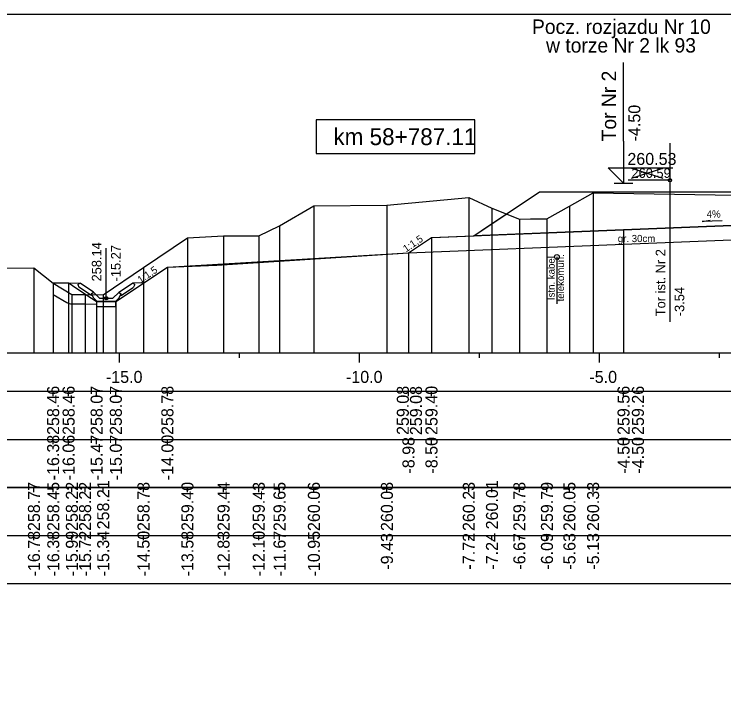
# Model space of a CAD drawing. Extents: x 6516023 to 6560129, y 5513077 to 5529206.
# Drawn here: x 6516933.52 to 6516948.3, y 5514498.91 to 5514513.16 of the extents above; entities that cross this region are included whole.
import ezdxf

# ---------------------------------------------------------------- set-up
doc = ezdxf.new("R2010")
doc.units = 0
for name, color, linetype in [('IR_default', 7, 'Continuous'), ('TOR_PRZEK_P-kable', 7, 'Continuous'), ('TOR_PRZEK_P-komponent', 7, 'Continuous'), ('TOR_PRZEK_P-odwodnienie', 7, 'Continuous'), ('TOR_PRZEK_P-opisy', 7, 'Continuous'), ('TOR_PRZEK_P-tabelka istniejace', 7, 'Continuous'), ('TOR_PRZEK_P-tabelka projektowane', 7, 'Continuous'), ('TOR_PRZEK_P-teren istniejacy', 7, 'Continuous'), ('TOR_PRZEK_P-tory istniejace', 7, 'Continuous'), ('TOR_PRZEK_P-tory projektowane', 7, 'Continuous'), ('TOR_PRZEK_P-uklad odniesienia', 7, 'Continuous'), ('TOR_PRZEK_P-warstwa ochronna I', 7, 'Continuous'), ('TOR_PRZEK_P-warstwa ochronna II', 7, 'Continuous'), ('TOR_PS_T-skarpy projektowane', 7, 'Continuous'), ('TOR_RAMKI-ramka+tabelka 1', 7, 'Continuous')]:
    doc.layers.add(name, color=color, linetype=linetype)

msp = doc.modelspace()

# ---------------------------------------------------------------- linework, layer by layer
at = {"layer": 'IR_default'}
msp.add_lwpolyline([(6516934.332, 5514507.567), (6516934.588, 5514507.564), (6516934.655, 5514507.563), (6516934.726, 5514507.516), (6516934.745, 5514507.503), (6516935.135, 5514507.243), (6516935.24, 5514507.173), (6516935.555, 5514507.173), (6516935.64, 5514507.173), (6516936.487, 5514507.738), (6516936.713, 5514507.889), (6516937.739, 5514507.93), (6516941.734, 5514508.19), (6516941.734, 5514508.19), (6516942.213, 5514508.509), (6516942.399, 5514508.516), (6516943.093, 5514508.544), (6516943.382, 5514508.737), (6516944.463, 5514509.458), (6516945.202, 5514509.458), (6516947.963, 5514509.458), (6516948.174, 5514509.458), (6516948.963, 5514509.458)], dxfattribs=at)
at = {"layer": 'TOR_PRZEK_P-kable'}
msp.add_line((6516944.825, 5514508.104), (6516944.825, 5514507.13), dxfattribs=at)
msp.add_circle((6516944.825, 5514508.104), 0.05, dxfattribs=at)
at = {"layer": 'TOR_PRZEK_P-komponent'}
msp.add_lwpolyline([(6516944.463, 5514509.458), (6516947.963, 5514509.458), (6516948.963, 5514509.458), (6516952.463, 5514509.458), (6516953.013, 5514509.458), (6516956.513, 5514509.458), (6516957.598, 5514508.735), (6516954.013, 5514508.878), (6516952.763, 5514508.928), (6516952.713, 5514508.929), (6516951.463, 5514508.879), (6516950.713, 5514508.849), (6516948.463, 5514508.759), (6516946.213, 5514508.669), (6516943.093, 5514508.544)], close=True, dxfattribs=at)
at = {"layer": 'TOR_PRZEK_P-odwodnienie'}
for p, q in [((6516935.439, 5514507.243), (6516935.439, 5514508.287)), ((6516935.13, 5514507.302), (6516934.869, 5514507.477)), ((6516935.175, 5514507.369), (6516934.894, 5514507.556)), ((6516935.704, 5514507.369), (6516935.984, 5514507.556)), ((6516935.748, 5514507.302), (6516936.01, 5514507.477)), ((6516935.142, 5514507.319), (6516935.13, 5514507.302)), ((6516935.132, 5514507.338), (6516935.179, 5514507.362)), ((6516935.175, 5514507.369), (6516935.166, 5514507.357)), ((6516935.299, 5514507.243), (6516935.179, 5514507.362)), ((6516935.579, 5514507.243), (6516935.699, 5514507.362)), ((6516935.699, 5514507.362), (6516935.747, 5514507.338)), ((6516935.704, 5514507.369), (6516935.712, 5514507.357)), ((6516935.737, 5514507.319), (6516935.748, 5514507.302)), ((6516935.249, 5514507.173), (6516935.629, 5514507.173)), ((6516935.299, 5514507.243), (6516935.579, 5514507.243))]:
    msp.add_line(p, q, dxfattribs=at)
for points in [[(6516934.648, 5514507.568), (6516934.894, 5514507.556)], [(6516934.844, 5514507.529), (6516934.894, 5514507.556)], [(6516934.844, 5514507.529), (6516934.869, 5514507.477)], [(6516936.231, 5514507.568), (6516935.984, 5514507.556)], [(6516936.035, 5514507.529), (6516935.984, 5514507.556)], [(6516936.035, 5514507.529), (6516936.01, 5514507.477)], [(6516935.166, 5514507.357), (6516935.131, 5514507.338)], [(6516935.131, 5514507.338), (6516935.142, 5514507.319)], [(6516935.179, 5514507.243), (6516935.132, 5514507.338)], [(6516935.699, 5514507.243), (6516935.747, 5514507.338)], [(6516935.712, 5514507.357), (6516935.748, 5514507.338)], [(6516935.748, 5514507.338), (6516935.737, 5514507.319)], [(6516935.249, 5514507.173), (6516935.179, 5514507.243)], [(6516935.24, 5514507.173), (6516935.239, 5514507.174), (6516935.24, 5514507.173), (6516935.239, 5514507.173), (6516935.24, 5514507.173), (6516935.24, 5514507.173), (6516935.24, 5514507.173), (6516935.24, 5514507.174)], [(6516935.239, 5514507.173), (6516935.239, 5514507.174), (6516935.239, 5514507.173), (6516935.239, 5514507.173), (6516935.239, 5514507.173), (6516935.24, 5514507.173), (6516935.239, 5514507.173), (6516935.24, 5514507.174)], [(6516935.639, 5514507.173), (6516935.239, 5514507.173), (6516935.239, 5514507.073), (6516935.639, 5514507.073), (6516935.639, 5514507.173)], [(6516935.629, 5514507.173), (6516935.699, 5514507.243)], [(6516935.64, 5514507.173), (6516935.639, 5514507.174), (6516935.64, 5514507.173), (6516935.639, 5514507.173), (6516935.64, 5514507.173), (6516935.64, 5514507.173), (6516935.64, 5514507.173), (6516935.64, 5514507.174)], [(6516935.639, 5514507.173), (6516935.639, 5514507.174), (6516935.639, 5514507.173), (6516935.639, 5514507.173), (6516935.639, 5514507.173), (6516935.64, 5514507.173), (6516935.639, 5514507.173), (6516935.64, 5514507.174)]]:
    msp.add_lwpolyline(points, dxfattribs=at)
msp.add_circle((6516935.439, 5514507.243), 0.035, dxfattribs=at)
at = {"layer": 'TOR_PRZEK_P-opisy'}
msp.add_lwpolyline([(6516948.268, 5514508.857), (6516947.85, 5514508.838), (6516948.018, 5514508.866)], dxfattribs=at)
at = {"layer": 'TOR_PRZEK_P-tabelka istniejace'}
for p, q in [((6516933.933, 5514503.206), (6516933.933, 5514503.306)), ((6516934.336, 5514503.206), (6516934.336, 5514503.306)), ((6516934.723, 5514503.206), (6516934.723, 5514503.306)), ((6516934.998, 5514503.206), (6516934.998, 5514503.306)), ((6516935.375, 5514503.206), (6516935.375, 5514503.306)), ((6516936.215, 5514503.206), (6516936.215, 5514503.306)), ((6516937.13, 5514503.206), (6516937.13, 5514503.306)), ((6516937.882, 5514503.206), (6516937.882, 5514503.306)), ((6516938.616, 5514503.206), (6516938.616, 5514503.306)), ((6516939.048, 5514503.206), (6516939.048, 5514503.306)), ((6516939.764, 5514503.206), (6516939.764, 5514503.306)), ((6516941.285, 5514503.206), (6516941.285, 5514503.306)), ((6516942.99, 5514503.206), (6516942.99, 5514503.306)), ((6516943.473, 5514503.206), (6516943.473, 5514503.306)), ((6516944.043, 5514503.206), (6516944.043, 5514503.306)), ((6516944.618, 5514503.206), (6516944.618, 5514503.306)), ((6516945.086, 5514503.206), (6516945.086, 5514503.306)), ((6516945.579, 5514503.206), (6516945.579, 5514503.306)), ((6516909.663, 5514502.306), (6516993.463, 5514502.306)), ((6516933.933, 5514502.206), (6516933.933, 5514502.306)), ((6516934.336, 5514502.206), (6516934.336, 5514502.306)), ((6516934.723, 5514502.206), (6516934.723, 5514502.306)), ((6516934.998, 5514502.206), (6516934.998, 5514502.306)), ((6516935.375, 5514502.206), (6516935.375, 5514502.306)), ((6516936.215, 5514502.206), (6516936.215, 5514502.306)), ((6516937.13, 5514502.206), (6516937.13, 5514502.306)), ((6516937.882, 5514502.206), (6516937.882, 5514502.306)), ((6516938.616, 5514502.206), (6516938.616, 5514502.306)), ((6516939.048, 5514502.206), (6516939.048, 5514502.306)), ((6516939.764, 5514502.206), (6516939.764, 5514502.306)), ((6516941.285, 5514502.206), (6516941.285, 5514502.306)), ((6516942.99, 5514502.206), (6516942.99, 5514502.306)), ((6516943.473, 5514502.206), (6516943.473, 5514502.306)), ((6516944.043, 5514502.206), (6516944.043, 5514502.306)), ((6516944.618, 5514502.206), (6516944.618, 5514502.306)), ((6516945.086, 5514502.206), (6516945.086, 5514502.306)), ((6516945.579, 5514502.206), (6516945.579, 5514502.306))]:
    msp.add_line(p, q, dxfattribs=at)
for points in [[(6516945.579, 5514509.437), (6516945.579, 5514506.306), (6516945.579, 5514506.176), (6516945.579, 5514506.106)], [(6516942.99, 5514509.341), (6516942.99, 5514506.306), (6516942.99, 5514506.176), (6516942.99, 5514506.106)], [(6516939.764, 5514509.164), (6516939.764, 5514506.306), (6516939.764, 5514506.176), (6516939.764, 5514506.106)], [(6516941.285, 5514509.182), (6516941.285, 5514506.306), (6516941.285, 5514506.176), (6516941.285, 5514506.106)], [(6516943.473, 5514509.118), (6516943.473, 5514506.306), (6516943.473, 5514506.176), (6516943.473, 5514506.106)], [(6516945.086, 5514509.16), (6516945.086, 5514506.306), (6516945.086, 5514506.176), (6516945.086, 5514506.106)], [(6516944.043, 5514508.889), (6516944.043, 5514506.306), (6516944.043, 5514506.176), (6516944.043, 5514506.106)], [(6516944.618, 5514508.898), (6516944.618, 5514506.306), (6516944.618, 5514506.176), (6516944.618, 5514506.106)], [(6516939.048, 5514508.752), (6516939.048, 5514506.306), (6516939.048, 5514506.176), (6516939.048, 5514506.106)], [(6516937.13, 5514508.502), (6516937.13, 5514506.306), (6516937.13, 5514506.176), (6516937.13, 5514506.106)], [(6516937.882, 5514508.543), (6516937.882, 5514506.306), (6516937.882, 5514506.176), (6516937.882, 5514506.106)], [(6516938.616, 5514508.54), (6516938.616, 5514506.306), (6516938.616, 5514506.176), (6516938.616, 5514506.106)], [(6516933.933, 5514507.874), (6516933.933, 5514506.306), (6516933.933, 5514506.176), (6516933.933, 5514506.106)], [(6516936.215, 5514507.884), (6516936.215, 5514506.306), (6516936.215, 5514506.176), (6516936.215, 5514506.106)], [(6516934.336, 5514507.56), (6516934.336, 5514506.306), (6516934.336, 5514506.176), (6516934.336, 5514506.106)], [(6516934.723, 5514507.324), (6516934.723, 5514506.306), (6516934.723, 5514506.176), (6516934.723, 5514506.106)], [(6516934.998, 5514507.325), (6516934.998, 5514506.306), (6516934.998, 5514506.176), (6516934.998, 5514506.106)], [(6516935.375, 5514507.316), (6516935.375, 5514506.306), (6516935.375, 5514506.176), (6516935.375, 5514506.106)]]:
    msp.add_lwpolyline(points, dxfattribs=at)
msp.add_lwpolyline([(6516909.663, 5514503.306), (6516909.663, 5514501.306), (6516993.463, 5514501.306), (6516993.463, 5514503.306)], close=True, dxfattribs=at)
at = {"layer": 'TOR_PRZEK_P-tabelka projektowane'}
for p, q in [((6516934.333, 5514505.206), (6516934.333, 5514505.306)), ((6516934.655, 5514505.206), (6516934.655, 5514505.306)), ((6516935.239, 5514505.206), (6516935.239, 5514505.306)), ((6516935.639, 5514505.206), (6516935.639, 5514505.306)), ((6516936.713, 5514505.206), (6516936.713, 5514505.306)), ((6516941.734, 5514505.206), (6516941.734, 5514505.306)), ((6516942.213, 5514505.206), (6516942.213, 5514505.306)), ((6516946.213, 5514505.206), (6516946.213, 5514505.306)), ((6516946.213, 5514505.206), (6516946.213, 5514505.306)), ((6516909.663, 5514504.306), (6516993.463, 5514504.306)), ((6516934.333, 5514504.206), (6516934.333, 5514504.306)), ((6516934.655, 5514504.206), (6516934.655, 5514504.306)), ((6516935.239, 5514504.206), (6516935.239, 5514504.306)), ((6516935.639, 5514504.206), (6516935.639, 5514504.306)), ((6516936.713, 5514504.206), (6516936.713, 5514504.306)), ((6516941.734, 5514504.206), (6516941.734, 5514504.306)), ((6516942.213, 5514504.206), (6516942.213, 5514504.306)), ((6516946.213, 5514504.206), (6516946.213, 5514504.306)), ((6516946.213, 5514504.206), (6516946.213, 5514504.306))]:
    msp.add_line(p, q, dxfattribs=at)
for points in [[(6516946.213, 5514508.669), (6516946.213, 5514506.306), (6516946.213, 5514506.176), (6516946.213, 5514506.106)], [(6516942.213, 5514508.509), (6516942.213, 5514506.306), (6516942.213, 5514506.176), (6516942.213, 5514506.106)], [(6516946.213, 5514508.369), (6516946.213, 5514506.306), (6516946.213, 5514506.176), (6516946.213, 5514506.106)], [(6516941.734, 5514508.19), (6516941.734, 5514506.306), (6516941.734, 5514506.176), (6516941.734, 5514506.106)], [(6516936.713, 5514507.889), (6516936.713, 5514506.306), (6516936.713, 5514506.176), (6516936.713, 5514506.106)], [(6516934.333, 5514507.566), (6516934.333, 5514506.306), (6516934.333, 5514506.176), (6516934.333, 5514506.106)], [(6516934.655, 5514507.563), (6516934.655, 5514506.306), (6516934.655, 5514506.176), (6516934.655, 5514506.106)], [(6516935.239, 5514507.173), (6516935.239, 5514506.306), (6516935.239, 5514506.176), (6516935.239, 5514506.106)], [(6516935.639, 5514507.173), (6516935.639, 5514506.306), (6516935.639, 5514506.176), (6516935.639, 5514506.106)]]:
    msp.add_lwpolyline(points, dxfattribs=at)
msp.add_lwpolyline([(6516909.663, 5514505.306), (6516909.663, 5514503.306), (6516993.463, 5514503.306), (6516993.463, 5514505.306)], close=True, dxfattribs=at)
at = {"layer": 'TOR_PRZEK_P-teren istniejacy'}
msp.add_lwpolyline([(6516930.633, 5514507.868), (6516933.933, 5514507.874), (6516934.336, 5514507.56), (6516934.723, 5514507.324), (6516934.998, 5514507.325), (6516935.375, 5514507.316), (6516936.215, 5514507.884), (6516937.13, 5514508.502), (6516937.882, 5514508.543), (6516938.616, 5514508.54), (6516939.048, 5514508.752), (6516939.764, 5514509.164), (6516941.285, 5514509.182), (6516942.99, 5514509.341), (6516943.473, 5514509.118), (6516944.043, 5514508.889), (6516944.277, 5514508.896), (6516944.618, 5514508.898), (6516945.086, 5514509.16), (6516945.579, 5514509.437), (6516951.077, 5514509.345)], dxfattribs=at)
at = {"layer": 'TOR_PRZEK_P-tory istniejace'}
for p, q in [((6516947.177, 5514510.474), (6516947.177, 5514506.754)), ((6516946.378, 5514509.746), (6516947.03, 5514509.949)), ((6516946.378, 5514509.949), (6516947.03, 5514509.746)), ((6516947.178, 5514509.699), (6516946.312, 5514509.699))]:
    msp.add_line(p, q, dxfattribs=at)
msp.add_circle((6516947.178, 5514509.699), 0.035, dxfattribs=at)
at = {"layer": 'TOR_PRZEK_P-tory projektowane'}
for p, q in [((6516946.213, 5514510.515), (6516946.213, 5514512.148)), ((6516946.213, 5514510.515), (6516946.213, 5514509.638)), ((6516946.213, 5514509.638), (6516945.894, 5514509.957)), ((6516945.894, 5514509.957), (6516947.238, 5514509.957)), ((6516946.021, 5514509.638), (6516946.405, 5514509.638))]:
    msp.add_line(p, q, dxfattribs=at)
at = {"layer": 'TOR_PRZEK_P-uklad odniesienia'}
for p, q in [((6516913.463, 5514506.106), (6516993.463, 5514506.106)), ((6516935.713, 5514505.906), (6516935.713, 5514506.106)), ((6516938.213, 5514506.006), (6516938.213, 5514506.106)), ((6516940.713, 5514505.906), (6516940.713, 5514506.106)), ((6516943.213, 5514506.006), (6516943.213, 5514506.106)), ((6516945.713, 5514505.906), (6516945.713, 5514506.106)), ((6516948.213, 5514506.006), (6516948.213, 5514506.106))]:
    msp.add_line(p, q, dxfattribs=at)
msp.add_lwpolyline([(6516943.113, 5514510.956), (6516939.813, 5514510.956), (6516939.813, 5514510.256), (6516943.113, 5514510.256)], close=True, dxfattribs=at)
at = {"layer": 'TOR_PRZEK_P-warstwa ochronna I'}
msp.add_lwpolyline([(6516941.734, 5514508.19), (6516946.213, 5514508.369), (6516948.463, 5514508.459), (6516950.713, 5514508.549), (6516952.713, 5514508.629), (6516952.763, 5514508.628), (6516954.013, 5514508.578), (6516954.763, 5514508.548), (6516959.715, 5514508.35)], dxfattribs=at)
at = {"layer": 'TOR_PRZEK_P-warstwa ochronna II'}
msp.add_lwpolyline([(6516934.333, 5514507.566), (6516934.655, 5514507.563), (6516935.239, 5514507.173), (6516935.639, 5514507.173), (6516936.713, 5514507.889), (6516941.734, 5514508.19), (6516942.213, 5514508.509), (6516946.213, 5514508.669), (6516948.463, 5514508.759), (6516950.713, 5514508.849), (6516951.463, 5514508.879), (6516952.713, 5514508.929), (6516952.763, 5514508.928), (6516954.013, 5514508.878), (6516954.763, 5514508.848), (6516959.063, 5514508.676), (6516959.932, 5514508.241), (6516962.429, 5514506.993), (6516962.829, 5514506.993), (6516963.684, 5514507.563), (6516965.364, 5514507.58)], dxfattribs=at)
at = {"layer": 'TOR_PS_T-skarpy projektowane'}
msp.add_line((6516934.336, 5514507.325), (6516934.619, 5514507.153), dxfattribs=at)
msp.add_lwpolyline([(6516934.723, 5514507.124), (6516934.995, 5514507.125), (6516935.239, 5514507.119)], dxfattribs=at)
msp.add_arc((6516934.723, 5514507.324), 0.2, 238.7097, 270.185, dxfattribs=at)
at = {"layer": 'TOR_RAMKI-ramka+tabelka 1'}
msp.add_lwpolyline([(6516907.013, 5514513.156), (6517154.513, 5514513.156), (6517154.513, 5514484.656), (6516907.013, 5514484.656)], close=True, dxfattribs=at)

# ---------------------------------------------------------------- texts
at = {"layer": 'TOR_PRZEK_P-kable'}
for s, height, p in [('Istn. kabel', 0.14999, (6516944.78, 5514507.206)), ('telekomun.', 0.15, (6516944.974, 5514507.178))]:
    msp.add_text(s, height=height, rotation=90.0511, dxfattribs=at).set_placement(p)
at = {"layer": 'TOR_PRZEK_P-odwodnienie'}
for s, p in [('258.14', (6516935.339, 5514507.593)), ('-15.27', (6516935.739, 5514507.593))]:
    msp.add_text(s, height=0.2, rotation=90, dxfattribs=at).set_placement(p)
at = {"layer": 'TOR_PRZEK_P-opisy'}
for s, rotation, p in [('4%', 0.1515, (6516947.945, 5514508.922)), ('1:1,5', 34.0701, (6516941.683, 5514508.195)), ('1:1,5', 34.0701, (6516936.153, 5514507.548))]:
    msp.add_text(s, height=0.15, rotation=rotation, dxfattribs=at).set_placement(p)
at = {"layer": 'TOR_PRZEK_P-tabelka istniejace'}
for s, p in [('258.77', (6516934.058, 5514502.398)), ('258.45', (6516934.461, 5514502.397)), ('258.22', (6516934.848, 5514502.4)), ('258.22', (6516935.123, 5514502.4)), ('258.21', (6516935.5, 5514502.433)), ('258.78', (6516936.34, 5514502.398)), ('259.40', (6516937.255, 5514502.398)), ('259.44', (6516938.007, 5514502.399)), ('259.43', (6516938.741, 5514502.398)), ('259.65', (6516939.173, 5514502.397)), ('260.06', (6516939.889, 5514502.398)), ('260.08', (6516941.41, 5514502.398)), ('260.23', (6516943.115, 5514502.398)), ('260.01', (6516943.598, 5514502.433)), ('259.78', (6516944.168, 5514502.398)), ('259.79', (6516944.743, 5514502.398)), ('260.05', (6516945.211, 5514502.397)), ('260.33', (6516945.704, 5514502.398)), ('-16.78', (6516934.058, 5514501.454)), ('-16.38', (6516934.461, 5514501.454)), ('-15.99', (6516934.848, 5514501.455)), ('-15.72', (6516935.123, 5514501.456)), ('-15.34', (6516935.5, 5514501.455)), ('-14.50', (6516936.34, 5514501.455)), ('-13.58', (6516937.255, 5514501.454)), ('-12.83', (6516938.007, 5514501.454)), ('-12.10', (6516938.741, 5514501.455)), ('-11.67', (6516939.173, 5514501.455)), ('-10.95', (6516939.889, 5514501.453)), ('-9.43', (6516941.41, 5514501.594)), ('-7.72', (6516943.115, 5514501.596)), ('-7.24', (6516943.598, 5514501.595)), ('-6.67', (6516944.168, 5514501.594)), ('-6.09', (6516944.743, 5514501.594)), ('-5.63', (6516945.211, 5514501.594)), ('-5.13', (6516945.704, 5514501.594))]:
    msp.add_text(s, height=0.25, rotation=90, dxfattribs=at).set_placement(p)
at = {"layer": 'TOR_PRZEK_P-tabelka projektowane'}
for s, p in [('258.46', (6516934.458, 5514504.398)), ('258.46', (6516934.78, 5514504.398)), ('258.07', (6516935.364, 5514504.398)), ('258.07', (6516935.764, 5514504.398)), ('258.78', (6516936.838, 5514504.398)), ('259.08', (6516941.741, 5514504.398)), ('259.08', (6516942.015, 5514504.394)), ('259.40', (6516942.338, 5514504.398)), ('259.56', (6516946.338, 5514504.398)), ('259.26', (6516946.638, 5514504.398)), ('-16.38', (6516934.458, 5514503.454)), ('-16.06', (6516934.78, 5514503.454)), ('-15.47', (6516935.364, 5514503.455)), ('-15.07', (6516935.764, 5514503.455)), ('-14.00', (6516936.838, 5514503.455)), ('-8.98', (6516941.859, 5514503.594)), ('-8.50', (6516942.338, 5514503.594)), ('-4.50', (6516946.338, 5514503.594)), ('-4.50', (6516946.638, 5514503.594))]:
    msp.add_text(s, height=0.25, rotation=90, dxfattribs=at).set_placement(p)
at = {"layer": 'TOR_PRZEK_P-tory istniejace'}
msp.add_text('260.59', height=0.2, dxfattribs=at).set_placement((6516946.378, 5514509.749))
for s, rotation, p in [('Tor ist. Nr 2', 90.0511, (6516947.084, 5514506.869)), ('-3.54', 90, (6516947.478, 5514506.869))]:
    msp.add_text(s, height=0.2, rotation=rotation, dxfattribs=at).set_placement(p)
at = {"layer": 'TOR_PRZEK_P-tory projektowane'}
for s, height, rotation, p in [('Pocz. rozjazdu Nr 10', 0.3, 360, (6516944.307, 5514512.746)), ('w torze Nr 2 lk 93', 0.3, 360, (6516944.6, 5514512.358)), ('Tor Nr 2', 0.3, 90, (6516946.058, 5514510.509)), ('-4.50', 0.25, 90, (6516946.563, 5514510.508))]:
    msp.add_text(s, height=height, rotation=rotation, dxfattribs=at).set_placement(p)
msp.add_text('260.53', height=0.25, dxfattribs=at).set_placement((6516946.293, 5514510.018))
at = {"layer": 'TOR_PRZEK_P-uklad odniesienia'}
for s, height, p in [('km 58+787.11', 0.35, (6516940.17, 5514510.431)), ('-15.0', 0.25, (6516935.432, 5514505.481)), ('-10.0', 0.25, (6516940.432, 5514505.481)), ('-5.0', 0.25, (6516945.502, 5514505.481))]:
    msp.add_text(s, height=height, dxfattribs=at).set_placement(p)
at = {"layer": 'TOR_PRZEK_P-warstwa ochronna I'}
msp.add_text('gr. 30cm', height=0.15, dxfattribs=at).set_placement((6516946.094, 5514508.412))

doc.saveas('drawing.dxf')
